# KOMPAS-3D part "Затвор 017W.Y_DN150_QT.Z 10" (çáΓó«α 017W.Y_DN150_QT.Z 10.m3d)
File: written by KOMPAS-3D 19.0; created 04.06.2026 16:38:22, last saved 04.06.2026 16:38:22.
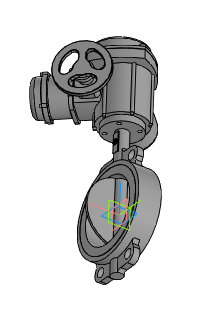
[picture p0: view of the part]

Document properties: Автор: Энергия; Полное имя файла: ..\..\..\3d для проектировщиков\017W разные\x.x Тип 017W.Y(S) Затвор дисковый поворотный межфланцевый\Затвор 017W.Y(S)_DN32-DN450_QT.Z\Затвор 017W.Y_DN150_QT.Z 10.a3d

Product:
- Part/product: Затвор 017W.Y_DN150_QT.Z 10
    Масса: 37.8655

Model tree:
1. Операция без истории:1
